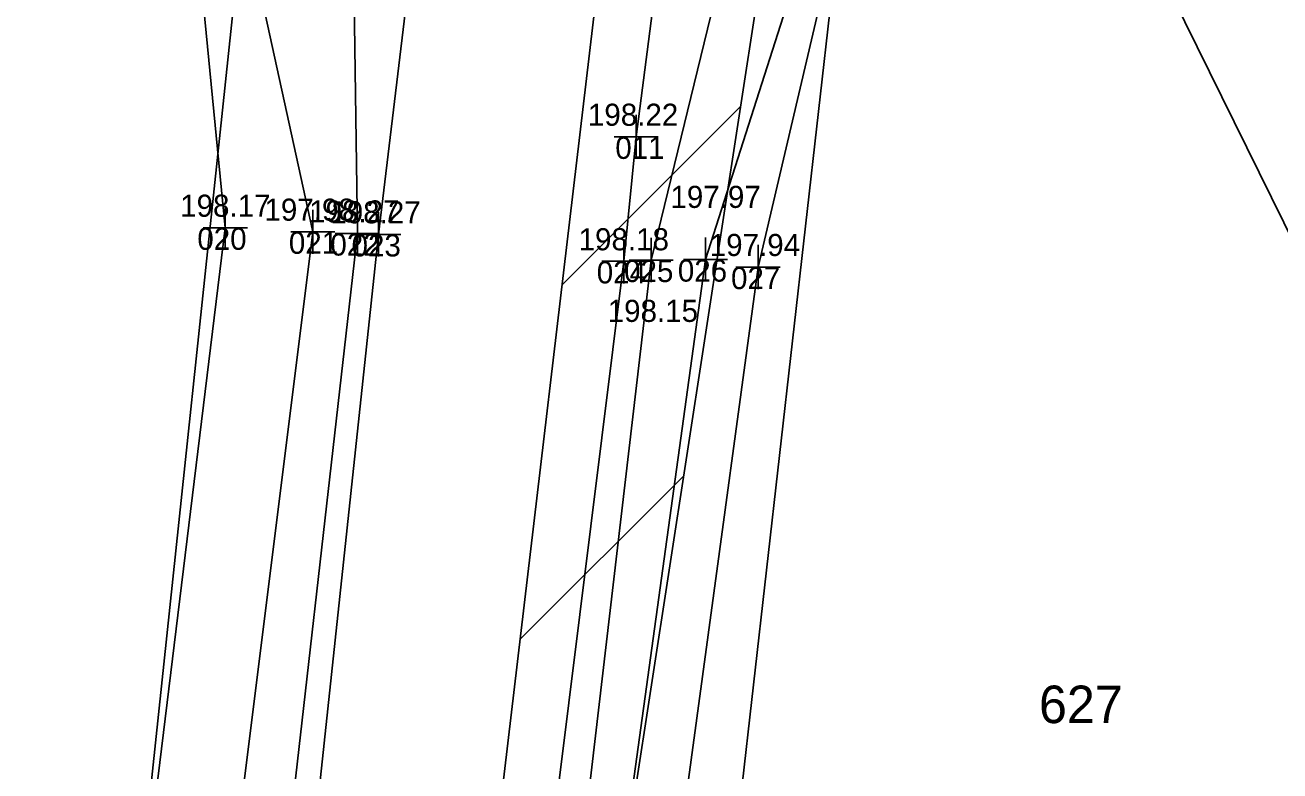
# Model space of a CAD drawing. Extents: x -706655 to -706193, y -1036183 to -1034979.
# Drawn here: x -706623.39 to -706594.99, y -1035140.99 to -1035124.1 of the extents above; entities that cross this region are included whole.
import ezdxf

# ---------------------------------------------------------------- set-up
doc = ezdxf.new("R2010")
doc.units = 0
for name, color, linetype in [('Hranice parcel', 7, 'Continuous'), ('křížky', 7, 'Continuous'), ('Nová vrstva (0)', 7, 'Continuous'), ('Nová vrstva (4)', 7, 'Continuous'), ('Parcelní čísla', 7, 'Continuous'), ('Stávající terén', 7, 'Continuous'), ('výšky', 7, 'Continuous'), ('čísla bodu', 7, 'Continuous')]:
    doc.layers.add(name, color=color, linetype=linetype)

msp = doc.modelspace()

# ---------------------------------------------------------------- linework, layer by layer
at = {"layer": 'Hranice parcel'}
for p, q in [((-706617.66, -1035114.1), (-706620.85, -1035144.24)), ((-706604.25, -1035115.63), (-706609.53, -1035162.16))]:
    msp.add_line(p, q, dxfattribs=at)
at = {"layer": 'křížky'}
for p, q in [((-706609.56, -1035127.13), (-706609.56, -1035126.13)), ((-706610.06, -1035126.63), (-706609.06, -1035126.63)), ((-706609.56, -1035126.63), (-706609.56, -1035126.63)), ((-706618.86, -1035129.19), (-706618.86, -1035128.19)), ((-706616.88, -1035129.28), (-706616.88, -1035128.28)), ((-706615.87, -1035129.32), (-706615.87, -1035128.32)), ((-706615.39, -1035129.34), (-706615.39, -1035128.34)), ((-706619.36, -1035128.69), (-706618.36, -1035128.69)), ((-706618.86, -1035128.69), (-706618.86, -1035128.69)), ((-706617.38, -1035128.78), (-706616.38, -1035128.78)), ((-706616.88, -1035128.78), (-706616.88, -1035128.78)), ((-706616.37, -1035128.82), (-706615.37, -1035128.82)), ((-706615.89, -1035128.84), (-706614.89, -1035128.84)), ((-706615.87, -1035128.82), (-706615.87, -1035128.82)), ((-706615.39, -1035128.84), (-706615.39, -1035128.84)), ((-706609.84, -1035129.95), (-706609.84, -1035128.95)), ((-706609.22, -1035129.92), (-706609.22, -1035128.92)), ((-706607.99, -1035129.91), (-706607.99, -1035128.91)), ((-706606.8, -1035130.08), (-706606.8, -1035129.08)), ((-706610.34, -1035129.45), (-706609.34, -1035129.45)), ((-706609.84, -1035129.45), (-706609.84, -1035129.45)), ((-706609.72, -1035129.42), (-706608.72, -1035129.42)), ((-706609.22, -1035129.42), (-706609.22, -1035129.42)), ((-706608.49, -1035129.41), (-706607.49, -1035129.41)), ((-706607.99, -1035129.41), (-706607.99, -1035129.41)), ((-706607.3, -1035129.58), (-706606.3, -1035129.58)), ((-706606.8, -1035129.58), (-706606.8, -1035129.58))]:
    msp.add_line(p, q, dxfattribs=at)
at = {"layer": 'Nová vrstva (0)'}
msp.add_line((-706589.39, -1035139.77), (-706604.84, -1035108.37), dxfattribs=at)
at = {"layer": 'Nová vrstva (4)'}
for p, q in [((-706608.43, -1035106.29), (-706622.552, -1035225.456)), ((-706604.229, -1035106.738), (-706622.552, -1035225.456)), ((-706611.239, -1035129.992), (-706607.194, -1035125.947)), ((-706612.19, -1035138.014), (-706608.484, -1035134.309))]:
    msp.add_line(p, q, dxfattribs=at)
at = {"layer": 'Stávající terén'}
for points in [[(-706608.917, -1035075.29), (-706610.31, -1035086.81), (-706611.88, -1035099.66), (-706615.39, -1035128.84), (-706617.25, -1035146.23)], [(-706612.08, -1035147.45), (-706609.84, -1035129.45), (-706609.56, -1035126.63), (-706608.3, -1035116.88), (-706606.85, -1035102.94), (-706605.26, -1035087.23), (-706604.17, -1035076.55)], [(-706630.18, -1035109.2), (-706620.44, -1035112.49), (-706618.86, -1035128.69), (-706620.88, -1035145.19)], [(-706620.44, -1035112.49), (-706616.88, -1035128.78), (-706618.96, -1035145.46)], [(-706620.44, -1035112.49), (-706616.05, -1035116.18), (-706615.87, -1035128.82), (-706617.82, -1035146.02)], [(-706611.34, -1035147.55), (-706609.22, -1035129.42), (-706605.99, -1035116.17), (-706603.37, -1035114.97)], [(-706610.51, -1035147.67), (-706607.99, -1035129.41), (-706603.37, -1035114.97)], [(-706609.32, -1035148.12), (-706606.8, -1035129.58), (-706603.37, -1035114.97)]]:
    msp.add_lwpolyline(points, dxfattribs=at)
at = {"layer": 'čísla bodu'}
for p, q in [((-706609.56, -1035127.13), (-706609.56, -1035126.13)), ((-706610.06, -1035126.63), (-706609.06, -1035126.63)), ((-706609.56, -1035126.63), (-706609.56, -1035126.63)), ((-706618.86, -1035129.19), (-706618.86, -1035128.19)), ((-706616.88, -1035129.28), (-706616.88, -1035128.28)), ((-706615.87, -1035129.32), (-706615.87, -1035128.32)), ((-706615.39, -1035129.34), (-706615.39, -1035128.34)), ((-706619.36, -1035128.69), (-706618.36, -1035128.69)), ((-706618.86, -1035128.69), (-706618.86, -1035128.69)), ((-706617.38, -1035128.78), (-706616.38, -1035128.78)), ((-706616.88, -1035128.78), (-706616.88, -1035128.78)), ((-706616.37, -1035128.82), (-706615.37, -1035128.82)), ((-706615.89, -1035128.84), (-706614.89, -1035128.84)), ((-706615.87, -1035128.82), (-706615.87, -1035128.82)), ((-706615.39, -1035128.84), (-706615.39, -1035128.84)), ((-706609.84, -1035129.95), (-706609.84, -1035128.95)), ((-706609.22, -1035129.92), (-706609.22, -1035128.92)), ((-706607.99, -1035129.91), (-706607.99, -1035128.91)), ((-706606.8, -1035130.08), (-706606.8, -1035129.08)), ((-706610.34, -1035129.45), (-706609.34, -1035129.45)), ((-706609.84, -1035129.45), (-706609.84, -1035129.45)), ((-706609.72, -1035129.42), (-706608.72, -1035129.42)), ((-706609.22, -1035129.42), (-706609.22, -1035129.42)), ((-706608.49, -1035129.41), (-706607.49, -1035129.41)), ((-706607.99, -1035129.41), (-706607.99, -1035129.41)), ((-706607.3, -1035129.58), (-706606.3, -1035129.58)), ((-706606.8, -1035129.58), (-706606.8, -1035129.58))]:
    msp.add_line(p, q, dxfattribs=at)

# ---------------------------------------------------------------- texts
at = {"layer": 'Parcelní čísla'}
msp.add_text('627', height=0.85, dxfattribs=at).set_placement((-706600.441, -1035139.909))
at = {"layer": 'výšky'}
for s, p in [('198.22', (-706610.652, -1035126.38)), ('198.17', (-706619.882, -1035128.44)), ('197.97', (-706608.784, -1035128.24)), ('197.98', (-706617.974, -1035128.53)), ('198.27', (-706616.962, -1035128.57)), ('198.27', (-706616.482, -1035128.59)), ('198.18', (-706610.862, -1035129.2)), ('197.94', (-706607.894, -1035129.33)), ('198.15', (-706610.204, -1035130.822))]:
    msp.add_text(s, height=0.5, dxfattribs=at).set_placement(p)
at = {"layer": 'čísla bodu'}
for s, p in [('011', (-706610.032, -1035127.13)), ('020', (-706619.494, -1035129.19)), ('021', (-706617.422, -1035129.28)), ('022', (-706616.482, -1035129.32)), ('023', (-706616.002, -1035129.34)), ('024', (-706610.452, -1035129.95)), ('025', (-706609.832, -1035129.92)), ('026', (-706608.616, -1035129.91)), ('027', (-706607.412, -1035130.08))]:
    msp.add_text(s, height=0.5, dxfattribs=at).set_placement(p)

doc.saveas('drawing.dxf')
